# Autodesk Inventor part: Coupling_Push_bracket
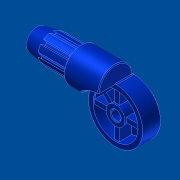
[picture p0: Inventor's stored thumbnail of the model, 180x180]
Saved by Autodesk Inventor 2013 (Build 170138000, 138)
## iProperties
Shininess: 69.0
Length Units: 11269
Angle Units: 11279
Time Units: 11290
Mass Units: 11283
Length Display Precision: 3
Angle Display Precision: 2
Created: 2001-04
Part Number: Coupling_Push_bracket
Material: Standard
Document SubType Name: Modellieren
Designer: dl
Density: 1 g/cm^3
Density: 0.0
Volumn: 0.0
Area: 0.0
PropertySet Name: Model Information
Control State: 0
Master: False
Checked Out: False
Author: dl
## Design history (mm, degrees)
sketch "Sketch1"
  geometry: C1 r 17.5 at (0, 0)
  constraints: 1 centre point
  dimensions: "d0" = 35 diameter of C1
extrude "Extrusion1" new body sketch "Sketch1" distance "d1" = 12; taper "d2" = 0 deg
sketch "Sketch4"
  geometry: C1 r 6.1 at (0, 0) reference; C2 r 17.5 at (0, 0); A1 r 17.5 centre (0, 0) between (-16.248, 6.5) and (0, 17.5) reference
  constraints: 1 centre point, 1 coincident, 1 concentric
extrude "Extrusion4" join sketch "Sketch4" stored distance "d38" = 9; taper "d39" = 0 deg
sketch "Sketch7"
  geometry: L1 (-9.022, 6.9)-(-5.242, 3.12); L2 (-6.9, 9.022)-(-3.12, 5.242); L3 (-1.5, 14.422)-(-6.9, 9.022); L4 (-9.022, 6.9)-(-14.422, 1.5); A1 r 14.5 centre (0, 0) between (-14.422, -1.5) and (-1.5, -14.422) reference; A2 r 14.5 centre (0, 0) between (-1.5, 14.422) and (-14.422, 1.5) reference; A3 r 6.1 centre (0, 0) between (-1.5, 5.913) and (-5.913, 1.5) reference
  constraints: 8 end point, 2 perpendicular, 2 point on circle, 1 parallel
  dimensions: "d43" = 1.5 distance from line of A1.centre L2; "d44" = 3 distance from line of L2 L1.end
extrude "Extrusion5" join sketch "Sketch7" stored distance "d45" = 9; taper "d46" = 0 deg
sketch "Sketch6"
  geometry: L1 (-1.5, 14.422)-(-1.5, 5.913); L2 (1.5, 14.422)-(1.5, 5.913); A1 r 14.5 centre (0, 0) between (-1.5, 14.422) and (1.5, 14.422) reference; A2 r 17.5 centre (0, 0) between (-16.248, 6.5) and (0, 17.5) reference; A3 r 14.5 centre (0, 0) between (-1.5, 14.422) and (1.5, 14.422) reference; A4 r 6.1 centre (0, 0) between (1.5, 5.913) and (-1.5, 5.913) reference
  constraints: 6 point on circle, 4 end point, 1 parallel, 1 vertical
  dimensions: "d36" = 3 distance between parallel lines of L1 L2; "d37" = 1.5 distance from line of A2.centre L2 (= 0.5 x d36)
extrude "Extrusion6" join sketch "Sketch6" distance "d78" = 25; taper "d79" = 0 deg
sketch "Sketch11"
  geometry: C1 r 3.6 at (0, 0) reference; 4 further points
  constraints: 2 coincident, 6 other
extrude "Extrusion7" cut sketch "Sketch11" distance "d98" = 1; taper "d99" = 0 deg
body "Solid1"
sketch "Sketch2"
  geometry: A1 r 17.5 centre (0, 0) between (0, 17.5) and (16.248, 6.5) reference; 1 further point
  constraints: 1 coincident
hole "Hole1" sketch "Sketch2" diameter "d14" = 6.2; stored, may be unused: countersink angle "d18" = 60 deg, drill point angle "d20" = 118 deg; dims "d15" = 6, "d16" = 4, "d17" = 2, "d19" = 8
shell "Shell1" dims "d31" = 3
revolve "Revolution1" stored, may be unused: angle "d28" = 90 deg
extrude "Extrusion2" cut sketch "Sketch4" distance "d32" = 12; taper "d33" = 0 deg
sketch "Sketch5"
  geometry: C1 r 3.1 at (0, 0) reference; C2 r 14.5 at (0, 0); C3 r 6.1 at (0, 0)
  constraints: 2 centre point, 2 coincident
extrude "Extrusion3" cut sketch "Sketch5" distance "d34" = 9; taper "d35" = 0 deg
pattern_circular "Circular Pattern1" dims angle "d42" = 360 deg
chamfer "Chamfer1" distance "d47" = 0.5; stored, may be unused: second distance "d48" = 0.5, angle "d100" = 45 deg
sketch "Sketch8"
  geometry: C1 r 6.737 at (0, 0) reference; 1 further point
  constraints: 1 coincident
hole "Hole2" sketch "Sketch8" diameter "d62" = 10; stored, may be unused: countersink angle "d66" = 60 deg, drill point angle "d68" = 0 deg; dims "d63" = 6, "d64" = 4, "d65" = 2, "d67" = 39
fillet "Fillet1" dims "d69" = 1
fillet "Fillet2" dims "d70" = 0.5
fillet "Fillet3" dims "d71" = 0.5
fillet "Fillet4" dims "d72" = 0.5
workaxis "Work Axis1"
workplane "Work Plane1"
pattern_circular "Circular Pattern2" dims angle "d88" = 360 deg
revolve "Revolution2" stored, may be unused: angle "d94" = 90 deg
sketch "Sketch3"
  geometry: L1 (0, 17.5)-(-51.5, 17.5); L2 (-51.5, 17.5)-(-51.5, 24.237); L3 (-51.5, 24.237)-(-41.5, 26); L4 (-41.5, 26)-(-22.5, 26); L5 (-22.5, 26)-(-22.5, 28.5); L6 (-22.5, 28.5)-(0, 28.5); L7 (0, 28.5)-(0, 17.5); 2 further points
  constraints: 14 end point, 3 horizontal, 2 parallel, 2 vertical, 2 vertical alignment, 1 perpendicular, 2 other
  dimensions: "d21" = 11 distance of L6.end L1.start; "d22" = 22.5 distance of L5.end L6.end; "d23" = 8.5 distance between parallel lines of L1 L4; "d24" = 10 horizontal distance of L2.end L3.end; "d25" = 10 deg angle of L3 L4; "d26" = 51.5 distance of L1.start L1.end; "d27" = 17.5 distance from line of point (0, 0) L1 (derived)
sketch "Sketch9"
  geometry: L1 (-0.75, 8.969)-(-1.322, 8.397); L2 (0.75, 8.969)-(1.371, 8.389); L3 (10.5, 0)-(0, 0) reference; L4 (0, 0)-(0, 9.777); A1 r 8.5 centre (0, 0) between (1.371, 8.389) and (-1.322, 8.397); A2 r 9 centre (0, 0) between (0.75, 8.969) and (-0.75, 8.969); 1 further point
  constraints: 6 end point, 4 point on circle, 2 centre point, 1 perpendicular, 3 other
  dimensions: "d73" = 9 radius of A2; "d75" = 1.5 distance of L2.start L1.start (= 2 x d74); "d76" = 0.75 horizontal distance of L3.end L1.start (= 0.5 x d75); "d77" = 45 deg angle of L4 L1
sketch "Sketch10"
  geometry: L1 (22.25, 9.911)-(40.25, 6.737); L2 (40.25, 6.737)-(40.25, 13.5); L3 (40.25, 13.5)-(22.25, 13.5); L4 (30.25, 13.5)-(30.25, 8.5); L5 (40.25, 5)-(40.25, -5) reference; L6 (40.25, 0)-(46.581, 0); L7 (54.114, 0)-(-51.349, 0) reference; L8 (22.25, 13.5)-(22.25, 9.911)
  constraints: 12 end point, 4 perpendicular, 2 point on line, 1 midpoint, 1 vertical
  dimensions: "d89" = 10 deg angle of L3 L1; "d90" = 0 distance between parallel lines of L5 L2; "d95" = 10 distance between parallel lines of L2 L4; "d96" = 18 distance of L2.end L3.end; "d97" = 8.5 distance from line of L6 L4.end
other parameters: "d3" = 11, "d53" = 7.767 (derived), "d74" = 0.75, "d80" = 0, "d81" = 0
